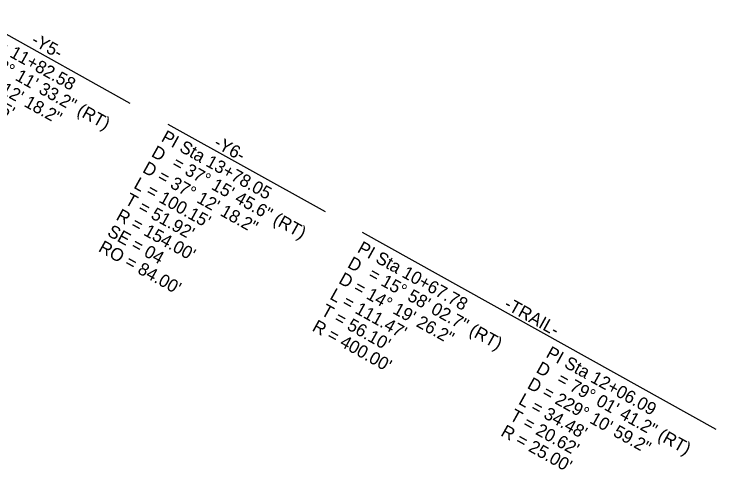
# Model space of a CAD drawing. Extents: x 1762196 to 1766326, y 709922 to 713142.
# Drawn here: x 1764729.9 to 1765117.1, y 711111 to 711362.6 of the extents above; entities that cross this region are included whole.
import ezdxf

# ---------------------------------------------------------------- set-up
doc = ezdxf.new("R2010")
doc.units = 0
doc.layers.add('Prop Horizontal Alignment Curve and Spiral Data', color=7, linetype='Continuous')

msp = doc.modelspace()

# ---------------------------------------------------------------- linework, layer by layer
at = {"layer": 'Prop Horizontal Alignment Curve and Spiral Data'}
for p, q in [((1764705.67, 711362.62), (1764793.89, 711313.5)), ((1764814.75, 711301.88), (1764901.51, 711253.57)), ((1764921.96, 711242.18), (1765117.05, 711133.54))]:
    msp.add_line(p, q, dxfattribs=at)

# ---------------------------------------------------------------- texts
for s, p in [('PI Sta 11+82.58', (1764702.5, 711352.94)), ('-Y5-', (1764738.89, 711346.32)), ('D = 37%%d 12\' 18.2"', (1764692.19, 711335.8)), ('= 38%%d 11\' 33.2" (RT)', (1764708.42, 711338.54)), ("L = 102.65'", (1764687.32, 711327.06)), ('PI Sta 13+78.05', (1764810.62, 711292.74)), ('-Y6-', (1764839.6, 711289.65)), ('D', (1764805.17, 711284.33)), ('D = 37%%d 12\' 18.2"', (1764800.3, 711275.59)), ('= 37%%d 15\' 45.6" (RT)', (1764816.54, 711278.33)), ("L = 100.15'", (1764795.44, 711266.85)), ("T = 51.92'", (1764790.57, 711258.12)), ("R = 154.00'", (1764785.7, 711249.38)), ('SE = 04', (1764780.84, 711240.64)), ("RO = 84.00'", (1764775.97, 711231.91)), ('PI Sta 10+67.78', (1764918.77, 711231.48)), ('D', (1764913.32, 711223.08)), ('D = 14%%d 19\' 26.2"', (1764908.46, 711214.34)), ('= 15%%d 58\' 02.7" (RT)', (1764924.69, 711217.08)), ("L = 111.47'", (1764903.59, 711205.6)), ('-TRAIL-', (1764999.62, 711200.54)), ("T = 56.10'", (1764898.72, 711196.87)), ("R = 400.00'", (1764893.86, 711188.13)), ('PI Sta 12+06.09', (1765022.8, 711173.55)), ('D', (1765017.35, 711165.14)), ('D = 229%%d 10\' 59.2"', (1765012.48, 711156.41)), ('= 79%%d 01\' 41.2" (RT)', (1765028.72, 711159.15)), ("L = 34.48'", (1765007.62, 711147.67)), ("T = 20.62'", (1765002.75, 711138.93)), ("R = 25.00'", (1764997.89, 711130.2))]:
    msp.add_text(s, height=7, rotation=330.8875, dxfattribs=at).set_placement(p)

doc.saveas('drawing.dxf')
